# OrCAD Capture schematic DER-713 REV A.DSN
size Custom; title: DER 712; rev: A
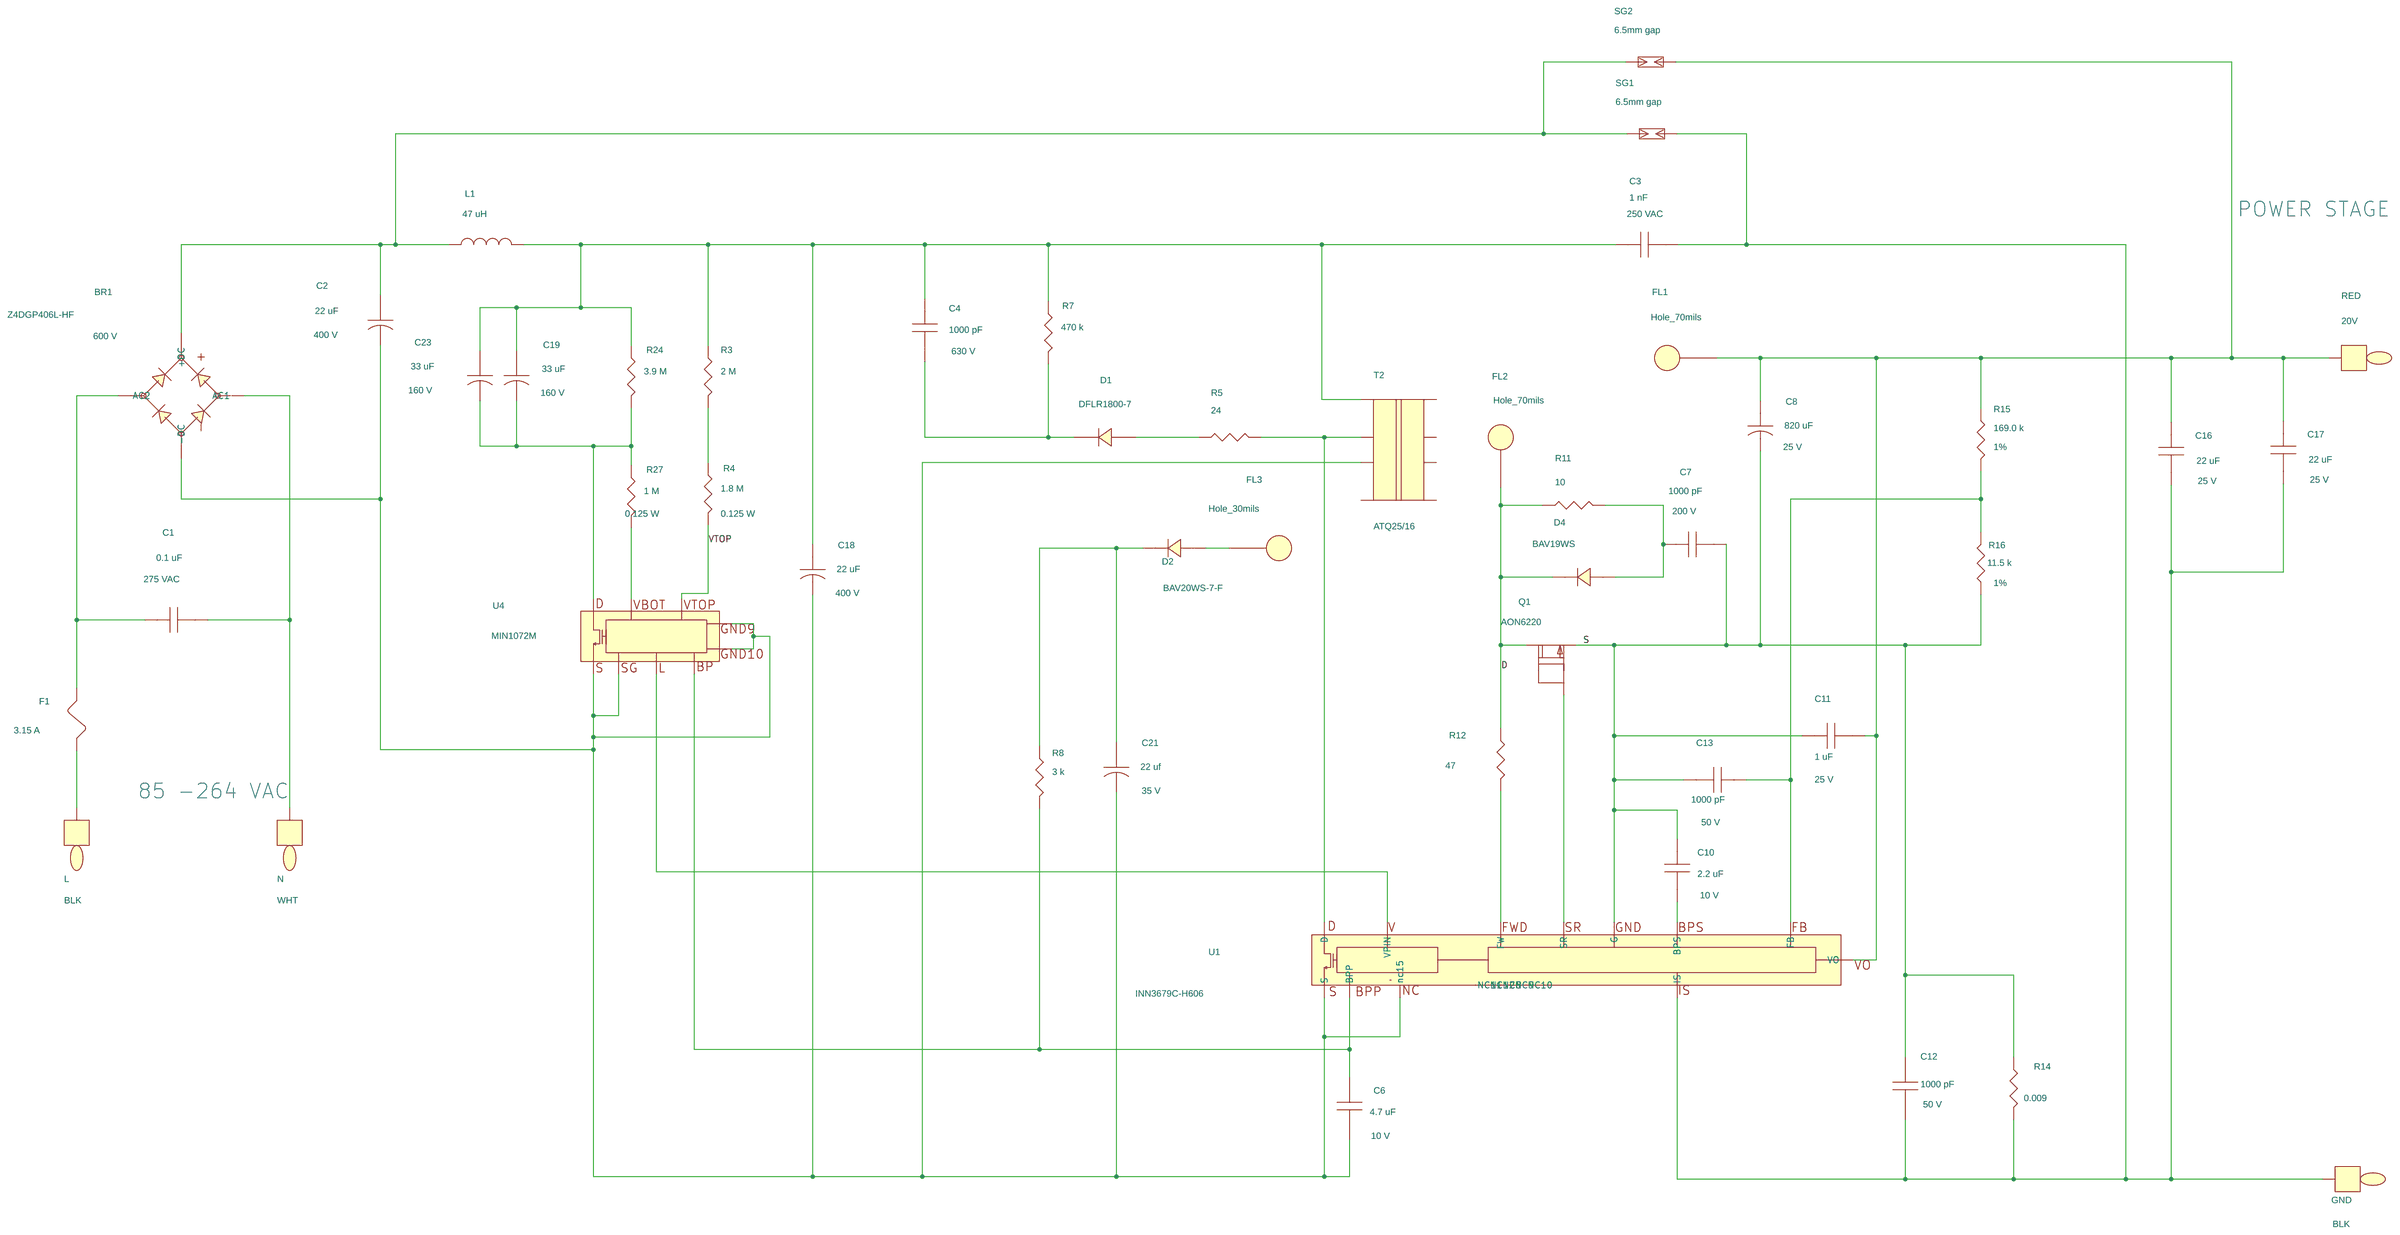
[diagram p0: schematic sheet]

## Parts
20V  RED  [pitpkeystone100x100]
BR1  Z4DGP406L-HF  [pi_sm_d_z4d]
C1  0.1 uF  [pinpxcaprad5x13x11p1mm040]
C2  22 uF  [pipolcapclyd320ls140030]
C3  1 nF  [pinpycaprad540x290ls400040]
C4  1000 pF  [pismc1206]
C6  4.7 uF  [pismc0805]
C7  1000 pF  [pismc0603]
C8  820 uF  [pipolcapclyd320ls140030]
C10  2.2 uF  [pismc0603]
C11  1 uF  [pismc0603]
C12  1000 pF  [pismr0402]
C13  1000 pF  [pismr0402]
C16  22 uF  [pismc0805]
C17  22 uF  [pismc0805]
C18  22 uF  [pipolcapclyd320ls140030]
C19  33 uF  [pipolcapclyd320ls140030]
C21  22 uf  [pipolcap4p0x11p0xls1p5d030]
C23  33 uF  [pipolcapclyd320ls140030]
D1  DFLR1800-7  [pismddflr120012]
D2  BAV20WS-7-F  [pismdsod323]
D4  BAV19WS  [pismsod323]
F1  3.15 A  [pi_rst_microfuse]
FL1  Hole_70mils  [pi_hole_70mil]
FL2  Hole_70mils  [pi_hole_70mil]
FL3  Hole_30mils  [pi_hole_30mil]
GND  BLK  [pitpkeystone100x100]
L  BLK  [pitpkeystone100x100]
L1  47 uH  [pichoketokinvd345h453ls197d030]
N  WHT  [pitpkeystone100x100]
Q1  AON6220  [pismpqfn5x6b]
R3  2 M  [pismr1206]
R4  1.8 M  [pi18wvresd80ls100d030]
R5  24  [pismr1206]
R7  470 k  [pismr1206]
R8  3 k  [pismr0603]
R11  10  [pismr1206]
R12  47  [pismr0603]
R14  0.009  [pismr0805]
R15  169.0 k  [pismr0402]
R16  11.5 k  [pismr0402]
R24  3.9 M  [pismr1206]
R27  1 M  [pi18wvresd80ls100d030]
SG1  6.5mm gap  [PI_SPARK_GAP_6p5MM]
SG2  6.5mm gap  [PI_SPARK_GAP_6p5MM]
T2  ATQ25/16  [pi_bobbin_ATQ25_H_8P]
U1  INN3679C-H606  [pi_ic_insop_24d]
U4  MIN1072M  [PI_SM_MinSOP16A_1]

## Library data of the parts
20V = TESTPOINT: Part Number: 35-00080-00
BR1 = DISCRETE_BRIDGE_+~~-: Disp_Voltage: 600 V; Part Number: 15-01613-00
C1 = CAP_NP: ALT_SYMBOLS: pinpxcaprad5x13x11p1mm040h; Disp_Voltage: 275 VAC; FPLIST: pinpxcaprad5x13x11p1mm040,pinpxcaprad5x13x11p1mm040h; Part Number: 20-09109-00; Voltage: 275 VAC
C2 C18 = CAP_POL: ALT_SYMBOLS: pipolcapclyd320ls140030h630; Disp_Voltage: 400 V; FPLIST: pipolcapclyd320ls140030,pipolcapclyd320ls140030430h,pipolcapclyd320ls140030h630; Part Number: 20-01315-00; Voltage: 400 V
C3 = CAP_NP: ALT_SYMBOLS: pinpycaprad540x290ls400040h,pinpycaprad500x220ls400040; Disp_Voltage: 250 VAC; FPLIST: pinpycaprad540x290ls400040,pinpycaprad540x290ls400040h,pinpycaprad500x220ls400040; Part Number: 20-00375-00; Voltage: 250 VAC
C4 = CAP_NP: Disp_Voltage: 630 V; Part Number: 20-08616-00; Voltage: 630 V
C6 = CAP_NP: Disp_Voltage: 10 V; Part Number: 20-01487-00; Voltage: 10 V
C7 = CAP_NP: Disp_Voltage: 200 V; Part Number: 20-09194-00; Voltage: 200 V
C8 = CAP_POL: Disp_Voltage: 25 V; Part Number: 20-01486-00; Voltage: 25 V
C10 = CAP_NP: ALT_SYMBOLS: pismc0603_1; Disp_Voltage: 10 V; FPLIST: pismc0603,pismc0603_1; Part Number: 20-08740-00; Voltage: 10V
C11 = CAP_NP: ALT_SYMBOLS: pismc0603_1; Disp_Voltage: 25 V; FPLIST: pismc0603,pismc0603_1; Part Number: 20-09147-00; Voltage: 25 V
C12 C13 = CAP_NP: ALT_SYMBOLS: pismr0402_1; Disp_Voltage: 50 V; FPLIST: pismr0402,pismr0402_1; Part Number: 20-09106-00; ROOM: 2; Voltage: 50 V
C16 C17 = CAP_NP: Disp_Voltage: 25 V; Part Number: 20-09216-00; Voltage: 25 V
C19 C23 = CAP_POL: Disp_Voltage: 160 V; Part Number: 20-01485-00; Voltage: 160 V
C21 = CAP_POL: ALT_SYMBOLS: pipolcap4p0x12p5xls1p5d030h; Disp_Voltage: 35 V; FPLIST: pipolcap4p0x11p0xls1p5d030,pipolcap4p0x12p5xls1p5d030h; Part Number: 20-01139-00; Voltage: 35 V
D1 = DIODE: COMPGROUP: 2; Part Number: 15-00919-00; ROOM: 1
D2 = DIODE: Part Number: 15-00712-00
D4 = DIODE: Part Number: 15-00658-00; ROOM: 2
F1 = FUSE: ALT_SYMBOLS: pirstmicrofusehoz; COMPGROUP: 1; FPLIST: pi_rst_microfuse,pirstmicrofusehoz; Part Number: 40-00020-00; ROOM: 1
FL1 FL2 = FlyingLead: Part Number: 35-00282-00; ROOM: 2
FL3 = FlyingLead: Part Number: 35-00284-00; ROOM: 2
GND L = TESTPOINT: ALT_SYMBOLS: TP_TH_CR2_D1_1; FPLIST: pitpkeystone100x100,TP_TH_CR2_D1_1; Part Number: 35-00079-00
L1 = INDUCTOR: ALT_SYMBOLS: pichoketokinvd345h453ls197d030H; FPLIST: pichoketokinvd345h453ls197d030,pichoketokinvd345h453ls197d030H; Part Number: 30-04098-00
N = TESTPOINT: Part Number: 35-00081-00
Q1 = FET_N_SGD_123_4_5678: Part Number: 50-00276-00; ROOM: 2
R3 = R: Part Number: 05-01428-00
R4 = R: ALT_SYMBOLS: pi18wresd080ls300d030; Disp_Power: 0.125 W; FPLIST: pi18wvresd80ls100d030,pi18wresd080ls300d030; Part Number: 05-02415-00
R5 = R: Part Number: 05-01313-00
R7 = R: Part Number: 05-01416-00
R8 = R: Part Number: 05-01699-00
R11 = R: Part Number: 05-01304-00
R12 = R: ALT_SYMBOLS: pismr0603_1; Part Number: 05-01656-00; ROOM: 2
R14 = R: Disp_Tol: 1%; Part Number: 05-06508-00
R15 = R: Disp_Tol: 1%; Part Number: 05-06060-00; ROOM: 2
R16 = R: Disp_Tol: 1%; Part Number: 05-05941-00; ROOM: 2
R24 = R: Part Number: 05-01435-00
R27 = R: ALT_SYMBOLS: pi18wresd080ls300d030; Disp_Power: 0.125 W; FPLIST: pi18wvresd80ls100d030,pi18wresd080ls300d030; Part Number: 05-02409-00
SG1 SG2 = SPARK_GAP: Part Number: 66-00360-00
T2 = BATQ25_8P_GENERIC: Part Number: 25-01167-00
U1 = Inno3EP_P15: Part Number: 10-01050-03
U4 = MinE-CAP: Part Number: 10-01091-00

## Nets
D: D4.1 FL2.1 Q1.5(D) R11.1 R12.1
NC8: U1.8(NC8)
NC9: U1.9(NC9)
NC10: U1.10(NC10)
NC11: U1.11(NC11)
NC12: U1.12(NC12)
S: C7.2 C8.2 C10.1 C11.1 C12.1 C13.2 Q1.1(S) R14.1 R16.1 U1.2(G)
VTOP: R4.2 U4.8
N10805923: BR1.4(-DC) C2.2 C6.2 C18.2 C21.2 T2.3 U1.15(nc15) U1.16(S) U4.3 U4.9 U4.10 U4.11
N10806149: C6.1 R8.2 U1.14(BPP) U4.4
N10808843: C3.2 C12.2 C16.2 C17.2 GND.1 R14.2 SG1.2 U1.1(IS)
N10813018: R3.2 R4.1
N10840366: BR1.1(+DC) C2.1 L1.1 SG1.1 SG2.1
N10873526: R12.2 U1.7(FW)
N10897256: C13.1 R15.2 R16.2 U1.3(FB)
N10950053: C21.1 D2.1 R8.1
N10961861: C3.1 C4.1 C18.1 C19.1 C23.1 L1.2 R3.1 R7.1 R24.1 T2.1
N10998999: 20V.1 C8.1 C11.2 C16.1 C17.1 FL1.1 R15.1 SG2.2 U1.6(VO)
N11099981: BR1.3(AC2) C1.1 F1.2
N11100037: BR1.2(AC1) C1.2 N.1
N11139529: C4.2 D1.1 R7.2
N11156493: C7.1 D4.2 R11.2
N12473754: C19.2 C23.2 R24.2 R27.1 U4.16
N12473992: U1.13(VPIN) U4.5
N12493844: R5.2 T2.2 U1.24(D)
N12496023: Q1.4(G) U1.5(SR)
N12509547: D1.2 R5.1
N12525421: F1.1 L.1
N12537489: R27.2 U4.1
N12549108: D2.2 FL3.1
N12562988: C10.2 U1.4(BPS)

Not connected (* = marked no-connect by the designer): Q1 2(S2) 3(S3) 6(D6) 7(D7) 8(D8); T2 4 5 6 7 8

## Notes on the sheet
- POWER STAGE
- 85 -264 VAC
